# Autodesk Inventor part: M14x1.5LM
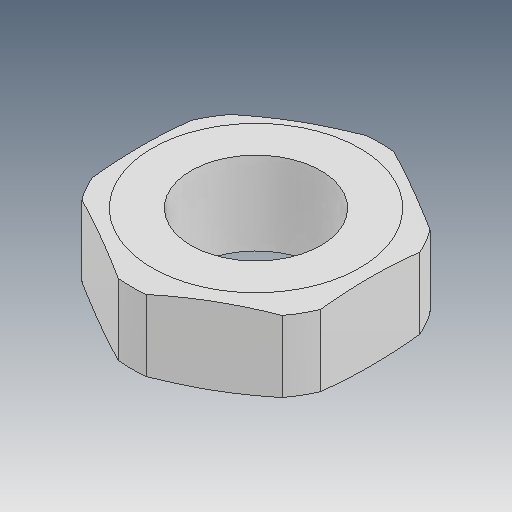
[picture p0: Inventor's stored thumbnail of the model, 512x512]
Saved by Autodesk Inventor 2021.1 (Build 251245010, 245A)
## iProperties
Created: 2021-05
Part Number: M14x1.5LM
Material: Ogólny
Document SubType Name: Modeling
Designer: user
Density: 1 g/cm^3
Appearance: Domyślna
Author: user
Revision Number: ÈÎºÎ
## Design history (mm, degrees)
feature "ÇÐ³ý-Ðý×ª1"
node "Bryła1"
